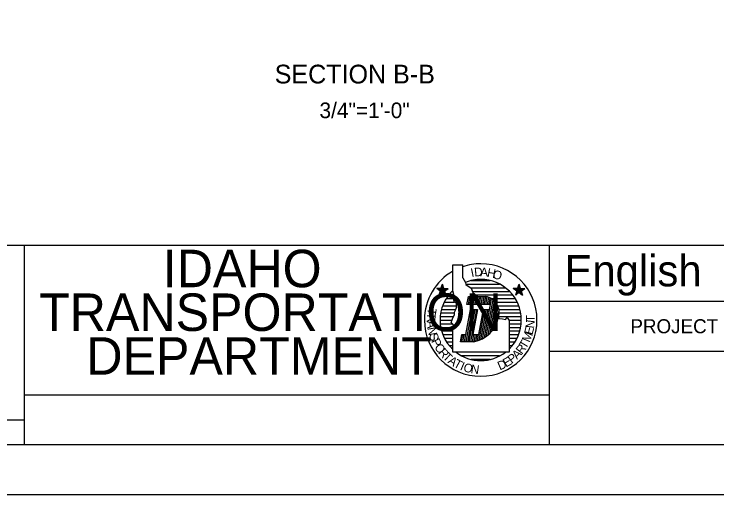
# Model space of a CAD drawing. Extents: x 0 to 136, y 0 to 94.
# Drawn here: x 55.59 to 83.7, y 0 to 19.24 of the extents above; entities that cross this region are included whole.
import ezdxf

# ---------------------------------------------------------------- set-up
doc = ezdxf.new("R2010")
doc.units = 0
for name, color, linetype in [('BORDER_ANNO_Cutsheet', 7, 'Continuous'), ('BRDG_ANNO_Anno-Sheet', 7, 'Continuous'), ('BRDG_ANNO_Anno-Small-Print', 7, 'Continuous'), ('BRDG_ANNO_General-Notes', 7, 'Continuous')]:
    doc.layers.add(name, color=color, linetype=linetype)

msp = doc.modelspace()

# ---------------------------------------------------------------- linework, layer by layer
at = {"layer": 'BORDER_ANNO_Cutsheet'}
msp.add_lwpolyline([(0, 88), (136, 88), (136, 0), (0, 0)], close=True, dxfattribs=at)
at = {"layer": 'BRDG_ANNO_Anno-Sheet'}
for p, q in [((6, 10), (77, 10)), ((56, 2), (56, 10)), ((77, 2), (77, 10)), ((77, 10), (134, 10)), ((73.138, 8.17), (73.138, 9.213)), ((73.138, 9.213), (73.532, 9.213)), ((73.532, 8.692), (73.532, 9.213)), ((73.532, 8.692), (73.638, 8.505)), ((73.638, 8.505), (73.657, 8.42)), ((73.86, 8.578), (74.632, 8.578)), ((72.805, 8.16), (72.49, 8.262)), ((72.662, 8.262), (72.49, 8.262)), ((72.63, 8.16), (72.49, 8.262)), ((72.772, 8.262), (72.575, 7.992)), ((72.63, 8.16), (72.575, 7.992)), ((72.63, 8.16), (72.947, 8.262)), ((72.662, 8.262), (72.718, 8.428)), ((72.662, 8.262), (72.86, 7.992)), ((72.718, 8.095), (72.718, 8.428)), ((72.772, 8.262), (72.718, 8.428)), ((72.772, 8.262), (72.947, 8.262)), ((72.805, 8.16), (72.947, 8.262)), ((72.805, 8.16), (72.86, 7.992)), ((73.177, 8.025), (73.138, 8.17)), ((73.657, 8.42), (73.865, 8.275)), ((73.668, 8.432), (75.002, 8.432)), ((73.86, 8.29), (75.227, 8.29)), ((73.865, 8.275), (73.93, 8.107)), ((75.87, 8.16), (75.552, 8.262)), ((75.695, 8.16), (75.552, 8.262)), ((75.727, 8.262), (75.552, 8.262)), ((75.837, 8.262), (75.64, 7.992)), ((75.695, 8.16), (75.64, 7.992)), ((75.695, 8.16), (76.01, 8.262)), ((75.727, 8.262), (75.782, 8.428)), ((75.727, 8.262), (75.925, 7.992)), ((75.782, 8.095), (75.782, 8.428)), ((75.837, 8.262), (75.782, 8.428)), ((75.837, 8.262), (76.01, 8.262)), ((75.87, 8.16), (76.01, 8.262)), ((75.87, 8.16), (75.925, 7.992)), ((72.718, 8.095), (72.575, 7.992)), ((72.718, 8.095), (72.86, 7.992)), ((72.968, 8.002), (73.175, 8.002)), ((73.097, 8.145), (73.145, 8.145)), ((73.177, 7.9), (73.177, 8.025)), ((73.177, 7.795), (73.177, 7.9)), ((73.7, 7.627), (73.763, 7.942)), ((73.757, 7.627), (73.815, 7.942)), ((73.763, 7.942), (74.45, 7.942)), ((73.82, 7.627), (73.88, 7.942)), ((73.885, 7.627), (73.942, 7.942)), ((73.915, 8.145), (75.403, 8.145)), ((73.93, 8.107), (74.138, 7.942)), ((73.947, 7.627), (74.007, 7.942)), ((74.01, 7.627), (74.07, 7.942)), ((74.062, 8.002), (75.53, 8.002)), ((74.075, 7.627), (74.132, 7.942)), ((74.138, 7.627), (74.197, 7.942)), ((74.203, 7.627), (74.26, 7.942)), ((74.265, 7.627), (74.325, 7.942)), ((74.33, 7.627), (74.388, 7.942)), ((74.392, 7.627), (74.453, 7.942)), ((74.455, 7.627), (74.513, 7.925)), ((74.52, 7.627), (74.572, 7.907)), ((74.582, 7.627), (74.63, 7.88)), ((75.782, 8.095), (75.64, 7.992)), ((75.782, 8.095), (75.925, 7.992)), ((72.787, 7.712), (73.192, 7.712)), ((72.867, 7.857), (73.17, 7.857)), ((73.2, 7.712), (73.177, 7.795)), ((73.282, 7.67), (73.2, 7.712)), ((73.282, 7.565), (73.282, 7.67)), ((74.645, 7.627), (73.7, 7.627)), ((74.397, 6.297), (74.688, 7.848)), ((74.47, 6.342), (74.745, 7.808)), ((74.545, 6.402), (74.797, 7.755)), ((74.608, 7.42), (74.645, 7.627)), ((74.623, 6.475), (74.85, 7.697)), ((74.675, 7.857), (75.63, 7.857)), ((74.703, 6.56), (74.9, 7.625)), ((74.84, 7.712), (75.71, 7.712)), ((77, 7.75), (89, 7.75)), ((72.683, 7.425), (73.245, 7.425)), ((72.725, 7.57), (73.275, 7.57)), ((73.2, 7.315), (73.24, 7.4)), ((73.2, 7.212), (73.2, 7.315)), ((73.24, 7.4), (73.282, 7.502)), ((73.282, 7.502), (73.282, 7.565)), ((73.657, 6.42), (73.845, 7.42)), ((73.665, 6.127), (73.907, 7.42)), ((73.73, 6.127), (73.972, 7.42)), ((73.793, 6.127), (74.035, 7.42)), ((73.845, 7.42), (74.12, 7.42)), ((73.858, 6.127), (74.1, 7.42)), ((74.12, 7.42), (73.933, 6.42)), ((74.175, 6.42), (74.362, 7.42)), ((74.188, 6.19), (74.418, 7.42)), ((74.255, 6.22), (74.48, 7.42)), ((74.325, 6.252), (74.545, 7.42)), ((74.362, 7.42), (74.608, 7.42)), ((74.787, 6.675), (74.947, 7.527)), ((74.888, 6.87), (74.983, 7.38)), ((74.93, 7.57), (75.772, 7.57)), ((74.977, 7.425), (75.817, 7.425)), ((72.63, 7.138), (73.162, 7.138)), ((72.65, 7.282), (73.192, 7.282)), ((73.115, 7.002), (73.138, 7.087)), ((73.138, 7.087), (73.2, 7.212)), ((74.962, 7.11), (74.992, 7.065)), ((74.97, 7.138), (75.87, 7.138)), ((74.99, 7.282), (75.85, 7.282)), ((74.992, 7.065), (75.117, 7.045)), ((75.117, 7.045), (75.242, 7.025)), ((75.242, 7.025), (75.305, 7.107)), ((75.305, 7.107), (75.388, 6.982)), ((72.625, 6.992), (73.11, 6.992)), ((72.632, 6.85), (73.125, 6.85)), ((73.075, 6.9), (73.115, 7.002)), ((73.138, 6.837), (73.075, 6.9)), ((73.177, 6.775), (73.138, 6.837)), ((73.2, 6.732), (73.177, 6.775)), ((75.38, 6.992), (75.875, 6.992)), ((75.388, 6.982), (75.388, 5.71)), ((75.39, 6.85), (75.867, 6.85)), ((72.653, 6.705), (73.192, 6.705)), ((72.685, 6.562), (73.135, 6.562)), ((73.138, 6.607), (73.2, 6.67)), ((73.138, 5.71), (73.138, 6.607)), ((73.2, 6.67), (73.2, 6.732)), ((75.388, 6.705), (75.847, 6.705)), ((75.388, 6.562), (75.815, 6.562)), ((72.735, 6.417), (73.13, 6.417)), ((72.797, 6.272), (73.13, 6.272)), ((73.438, 6.127), (73.492, 6.42)), ((73.475, 6.127), (73.53, 6.42)), ((73.492, 6.42), (73.657, 6.42)), ((73.54, 6.127), (73.595, 6.42)), ((73.602, 6.127), (73.657, 6.42)), ((73.92, 6.127), (73.975, 6.42)), ((73.933, 6.42), (74.175, 6.42)), ((73.985, 6.13), (74.04, 6.42)), ((74.052, 6.147), (74.102, 6.42)), ((74.12, 6.167), (74.165, 6.42)), ((75.388, 6.417), (75.765, 6.417)), ((75.388, 6.272), (75.7, 6.272)), ((72.88, 6.13), (73.132, 6.13)), ((72.983, 5.985), (73.13, 5.985)), ((73.97, 6.127), (73.438, 6.127)), ((75.388, 6.13), (75.62, 6.13)), ((75.388, 5.985), (75.52, 5.985)), ((73.11, 5.843), (73.135, 5.843)), ((75.388, 5.71), (73.138, 5.71)), ((77, 5.75), (89, 5.75)), ((75.002, 5.565), (73.487, 5.565)), ((74.635, 5.422), (73.87, 5.422)), ((56, 4), (77, 4))]:
    msp.add_line(p, q, dxfattribs=at)
msp.add_lwpolyline([(6, 86), (134, 86), (134, 2), (6, 2)], close=True, dxfattribs=at)
for centre, radius, start, end in [((74.25, 7), 2.25, 90, 108.596), ((74.25, 7), 2.25, 0, 90), ((74.25, 7), 2.25, 119.6331, 180), ((74.25, 7), 1.625, 90, 112.1452), ((74.25, 7), 1.625, 0, 90), ((74.25, 7), 1.625, 133.1926, 180), ((74.333, 7.296), 0.657, 343.4981, 79.7362), ((73.74, 7.353), 1.247, 280.6479, 348.7719), ((74.25, 7), 2.25, 180, 270), ((74.25, 7), 1.625, 180.2644, 226.7946), ((74.25, 7), 2.25, 270, 0), ((74.25, 7), 1.625, 314.427, 0), ((74.25, 7), 1.625, 232.5658, 270), ((74.25, 7), 1.625, 270, 307.4536)]:
    msp.add_arc(centre, radius, start, end, dxfattribs=at)
at = {"layer": 'BRDG_ANNO_Anno-Small-Print'}
msp.add_line((46, 3), (56, 3), dxfattribs=at)

# ---------------------------------------------------------------- texts
at = {"layer": 'BRDG_ANNO_Anno-Sheet'}
for s, height, p in [('IDAHO', 1.5, (61.535, 8.312)), ('English', 1.25, (77.602, 8.348)), ('TRANSPORTATION', 1.5, (56.587, 6.562)), ('PROJECT NO.', 0.5625, (80.237, 6.47)), ('DEPARTMENT', 1.5, (58.477, 4.812))]:
    msp.add_text(s, height=height, dxfattribs=at).set_placement(p)
for s, height, rotation, p in [('I', 0.347, 11.9519, (73.888, 8.713)), ('D', 0.348, 5.2118, (74.005, 8.737)), ('A', 0.347, 357.8718, (74.227, 8.752)), ('H', 0.348, 349.6318, (74.487, 8.735)), ('O', 0.348, 342.1917, (74.697, 8.692)), ('T', 0.348, 259.4265, (72.153, 7.502)), ('R', 0.347, 266.0275, (72.105, 7.23)), ('T', 0.347, 90.4926, (76.407, 6.917)), ('A', 0.348, 273.764, (72.093, 6.962)), ('N', 0.348, 83.1932, (76.38, 6.652)), ('N', 0.347, 280.3758, (72.115, 6.685)), ('S', 0.348, 287.9279, (72.172, 6.415)), ('M', 0.348, 67.7139, (76.203, 6.082)), ('E', 0.348, 75.6105, (76.317, 6.388)), ('P', 0.348, 295.4976, (72.263, 6.162)), ('T', 0.348, 59.0362, (76.055, 5.82)), ('O', 0.348, 302.6446, (72.382, 5.92)), ('R', 0.347, 52.3344, (75.895, 5.605)), ('R', 0.348, 309.9079, (72.535, 5.69)), ('T', 0.348, 317.1211, (72.71, 5.485)), ('P', 0.348, 37.6656, (75.492, 5.237)), ('A', 0.348, 45, (75.703, 5.402)), ('A', 0.348, 324.6375, (72.912, 5.303)), ('T', 0.348, 331.7503, (73.138, 5.147)), ('D', 0.348, 22.9887, (75.013, 4.982)), ('E', 0.348, 30.5476, (75.263, 5.095)), ('I', 0.348, 337.0213, (73.397, 5.015)), ('O', 0.348, 343.3287, (73.53, 4.962)), ('N', 0.348, 351.6598, (73.835, 4.88))]:
    msp.add_text(s, height=height, rotation=rotation, dxfattribs=at).set_placement(p)
at = {"layer": 'BRDG_ANNO_General-Notes'}
for s, height, p in [('SECTION B-B', 0.75, (66.01, 16.466)), ('3/4"=1\'-0"', 0.625, (67.801, 15.078))]:
    msp.add_text(s, height=height, dxfattribs=at).set_placement(p)

doc.saveas('drawing.dxf')
